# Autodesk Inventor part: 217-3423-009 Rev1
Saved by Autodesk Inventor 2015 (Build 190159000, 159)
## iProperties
Created: 2014-11
Part Number: 217-3423-009 Rev1
Material: Generic
Document SubType Name: Modeling
Designer: User
Density: 1 g/cm^3
Appearance: Default
Author: User
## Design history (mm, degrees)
node "217-3423-009 Rev1.ipt1"
node "#4-40 Tapped Hole2"
node "Base1"
